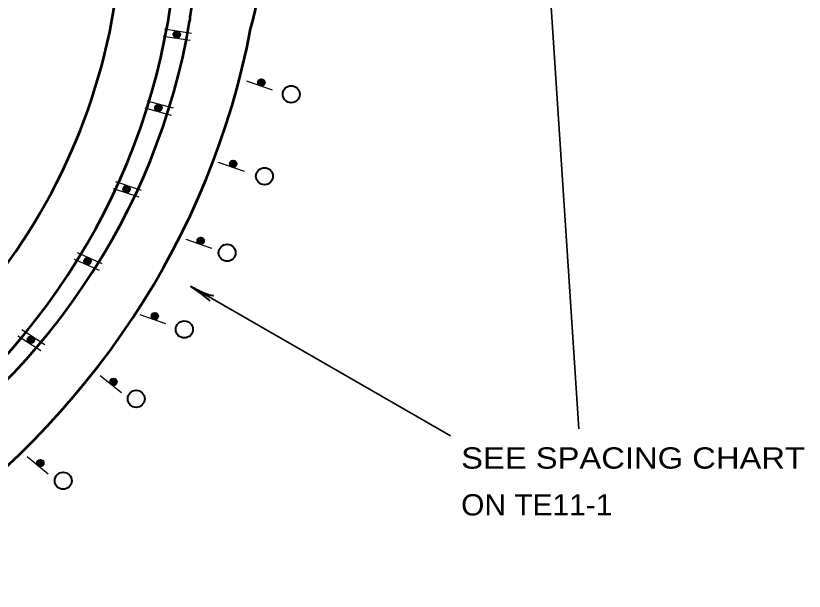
# Model space of a CAD drawing. Extents: x 393 to 1249, y -102 to 530.
# Drawn here: x 1022 to 1112, y 163.3 to 229 of the extents above; entities that cross this region are included whole.
import ezdxf

# ---------------------------------------------------------------- set-up
doc = ezdxf.new("R2010")
doc.units = 0
doc.header["$LTSCALE"] = 0.97
doc.layers.add('1', color=7, linetype='Continuous', lineweight=40)
doc.layers.add('4', color=7, linetype='Continuous', lineweight=25)

msp = doc.modelspace()

# ---------------------------------------------------------------- linework, layer by layer
at = {"layer": '1', "lineweight": 35}
for p, q in [((1078.9776, 294.0742), (1086.2967, 181.8469)), ((1041.9751, 198.1117), (1071.6584, 181.0337))]:
    msp.add_line(p, q, dxfattribs=at)
at = {"layer": '1'}
for centre, radius in [((1040.4098, 226.8492), 0.3791), ((1040.3987, 226.8411), 0.35), ((1040.4002, 226.8507), 0.3305), ((1040.4321, 226.8653), 0.3402), ((1040.4098, 226.8492), 0.3013), ((1040.4098, 226.8492), 0.2819), ((1040.4002, 226.8507), 0.2722), ((1040.4002, 226.8507), 0.2527), ((1040.4018, 226.8603), 0.2335), ((1040.4033, 226.8699), 0.2138), ((1040.4033, 226.8699), 0.1944), ((1040.381, 226.8537), 0.1555), ((1040.4063, 226.8891), 0.175), ((1040.3902, 226.9113), 0.1555), ((1040.4013, 226.9194), 0.1461), ((1040.3932, 226.9305), 0.1166), ((1040.3906, 226.8522), 0.1069), ((1040.3947, 226.9401), 0.0977), ((1040.3962, 226.9497), 0.0778), ((1040.3993, 226.9689), 0.0583), ((1040.4023, 226.9881), 0.0389), ((1040.4054, 227.0073), 0.0194), ((1040.5503, 226.8663), 0.00972), ((1050.0663, 221.3738), 0.3791), ((1050.0542, 221.3985), 0.3402), ((1050.0723, 221.3615), 0.35), ((1050.0755, 221.3706), 0.3305), ((1050.0663, 221.3738), 0.3013), ((1050.0663, 221.3738), 0.2819), ((1050.0755, 221.3706), 0.2722), ((1050.0755, 221.3706), 0.2527), ((1050.0786, 221.3798), 0.2335), ((1050.0818, 221.389), 0.2138), ((1050.0818, 221.389), 0.1944), ((1050.0881, 221.4074), 0.175), ((1050.0938, 221.3643), 0.1555), ((1049.9503, 221.4549), 0.00972), ((1050.1128, 221.4195), 0.1555), ((1050.1068, 221.4318), 0.1461), ((1050.0846, 221.3675), 0.1069), ((1050.1191, 221.4378), 0.1166), ((1050.1223, 221.447), 0.0977), ((1050.1255, 221.4562), 0.0778), ((1050.1318, 221.4746), 0.0583), ((1050.1381, 221.493), 0.0389), ((1050.1445, 221.5114), 0.0194), ((1053.4735, 220.025), 0.972), ((1038.3112, 218.4741), 0.3791), ((1038.2993, 218.4673), 0.35), ((1038.3018, 218.4767), 0.3305), ((1038.335, 218.4879), 0.3402), ((1038.3112, 218.4741), 0.3013), ((1038.3112, 218.4741), 0.2819), ((1038.3018, 218.4767), 0.2722), ((1038.3018, 218.4767), 0.2527), ((1038.3043, 218.486), 0.2335), ((1038.3068, 218.4954), 0.2138), ((1038.3068, 218.4954), 0.1944), ((1038.2981, 218.538), 0.1555), ((1038.31, 218.5449), 0.1461), ((1038.283, 218.4817), 0.1555), ((1038.3119, 218.5142), 0.175), ((1038.2924, 218.4792), 0.1069), ((1038.3031, 218.5568), 0.1166), ((1038.3057, 218.5662), 0.0977), ((1038.3082, 218.5756), 0.0778), ((1038.3132, 218.5943), 0.0583), ((1038.3182, 218.6131), 0.0389), ((1038.3233, 218.6319), 0.0194), ((1038.4527, 218.4765), 0.00972), ((1046.857, 212.084), 0.3791), ((1046.845, 212.1087), 0.3402), ((1046.8631, 212.0716), 0.35), ((1046.8662, 212.0808), 0.3305), ((1046.857, 212.084), 0.3013), ((1046.857, 212.084), 0.2819), ((1046.8662, 212.0808), 0.2722), ((1046.8662, 212.0808), 0.2527), ((1046.8694, 212.09), 0.2335), ((1046.8726, 212.0992), 0.2138), ((1046.8726, 212.0992), 0.1944), ((1046.8789, 212.1176), 0.175), ((1046.8846, 212.0745), 0.1555), ((1046.741, 212.1651), 0.00972), ((1046.9036, 212.1297), 0.1555), ((1046.8976, 212.142), 0.1461), ((1046.8754, 212.0777), 0.1069), ((1046.9099, 212.148), 0.1166), ((1046.9131, 212.1572), 0.0977), ((1046.9163, 212.1664), 0.0778), ((1046.9226, 212.1848), 0.0583), ((1046.9289, 212.2032), 0.0389), ((1046.9352, 212.2216), 0.0194), ((1050.4239, 210.6728), 0.972), ((1034.6835, 209.1901), 0.3791), ((1034.6712, 209.1838), 0.35), ((1034.6742, 209.1931), 0.3305), ((1034.708, 209.2026), 0.3402), ((1034.6835, 209.1901), 0.3013), ((1034.6835, 209.1901), 0.2819), ((1034.6742, 209.1931), 0.2722), ((1034.6742, 209.1931), 0.2527), ((1034.6772, 209.2023), 0.2335), ((1034.6802, 209.2116), 0.2138), ((1034.6802, 209.2116), 0.1944), ((1034.6557, 209.1991), 0.1555), ((1034.6863, 209.2301), 0.175), ((1034.6738, 209.2545), 0.1555), ((1034.686, 209.2608), 0.1461), ((1034.665, 209.1961), 0.1069), ((1034.6798, 209.273), 0.1166), ((1034.6828, 209.2823), 0.0977), ((1034.6858, 209.2915), 0.0778), ((1034.6918, 209.31), 0.0583), ((1034.6978, 209.3285), 0.0389), ((1034.7038, 209.347), 0.0194), ((1034.8249, 209.185), 0.00972), ((1043.1412, 203.3009), 0.3791), ((1043.1291, 203.3256), 0.3402), ((1043.1472, 203.2886), 0.35), ((1043.1504, 203.2978), 0.3305), ((1043.1412, 203.3009), 0.3013), ((1043.1412, 203.3009), 0.2819), ((1043.1504, 203.2978), 0.2722), ((1043.1504, 203.2978), 0.2527), ((1043.1535, 203.307), 0.2335), ((1043.1567, 203.3161), 0.2138), ((1043.1567, 203.3161), 0.1944), ((1043.163, 203.3345), 0.175), ((1043.1687, 203.2914), 0.1555), ((1043.0252, 203.382), 0.00972), ((1043.1877, 203.3466), 0.1555), ((1043.1817, 203.3589), 0.1461), ((1043.1595, 203.2946), 0.1069), ((1043.1941, 203.365), 0.1166), ((1043.1972, 203.3742), 0.0977), ((1043.2004, 203.3833), 0.0778), ((1043.2067, 203.4017), 0.0583), ((1043.213, 203.4201), 0.0389), ((1043.2194, 203.4385), 0.0194), ((1046.1544, 201.9306), 0.972), ((1030.2192, 200.9641), 0.3791), ((1030.2064, 200.9592), 0.35), ((1030.2103, 200.9681), 0.3305), ((1030.2449, 200.974), 0.3402), ((1030.2192, 200.9641), 0.3013), ((1030.2192, 200.9641), 0.2819), ((1030.2103, 200.9681), 0.2722), ((1030.2103, 200.9681), 0.2527), ((1030.2143, 200.977), 0.2335), ((1030.2182, 200.9858), 0.2138), ((1030.2182, 200.9858), 0.1944), ((1030.1926, 200.976), 0.1555), ((1030.2261, 201.0036), 0.175), ((1030.2163, 201.0293), 0.1555), ((1030.2291, 201.0342), 0.1461), ((1030.2014, 200.972), 0.1069), ((1030.2242, 201.047), 0.1166), ((1030.2281, 201.0559), 0.0977), ((1030.2321, 201.0648), 0.0778), ((1030.24, 201.0825), 0.0583), ((1030.2479, 201.1003), 0.0389), ((1030.2558, 201.1181), 0.0194), ((1030.3593, 200.9443), 0.00972), ((1037.9051, 194.6868), 0.3791), ((1037.893, 194.7115), 0.3402), ((1037.9111, 194.6745), 0.35), ((1037.9143, 194.6837), 0.3305), ((1037.9051, 194.6868), 0.3013), ((1037.9051, 194.6868), 0.2819), ((1037.9143, 194.6837), 0.2722), ((1037.9143, 194.6837), 0.2527), ((1037.9174, 194.6928), 0.2335), ((1037.9206, 194.702), 0.2138), ((1037.9206, 194.702), 0.1944), ((1037.9269, 194.7204), 0.175), ((1037.9327, 194.6773), 0.1555), ((1037.7891, 194.7679), 0.00972), ((1037.9516, 194.7325), 0.1555), ((1037.9456, 194.7448), 0.1461), ((1037.9235, 194.6805), 0.1069), ((1037.958, 194.7509), 0.1166), ((1037.9611, 194.76), 0.0977), ((1037.9643, 194.7692), 0.0778), ((1037.9706, 194.7876), 0.0583), ((1037.977, 194.806), 0.0389), ((1037.9833, 194.8244), 0.0194), ((1041.275, 193.1884), 0.972), ((1023.7523, 191.9966), 0.3791), ((1023.7388, 191.9938), 0.35), ((1023.7441, 192.0019), 0.3305), ((1023.7792, 192.0023), 0.3402), ((1023.7523, 191.9966), 0.3013), ((1023.7523, 191.9966), 0.2819), ((1023.7441, 192.0019), 0.2722), ((1023.7441, 192.0019), 0.2527), ((1023.7494, 192.0101), 0.2335), ((1023.7547, 192.0182), 0.2138), ((1023.7547, 192.0182), 0.1944), ((1023.7278, 192.0125), 0.1555), ((1023.7653, 192.0345), 0.175), ((1023.7596, 192.0614), 0.1555), ((1023.773, 192.0643), 0.1461), ((1023.736, 192.0072), 0.1069), ((1023.7702, 192.0777), 0.1166), ((1023.7755, 192.0859), 0.0977), ((1023.7807, 192.094), 0.0778), ((1023.7913, 192.1103), 0.0583), ((1023.8019, 192.1266), 0.0389), ((1023.8125, 192.1429), 0.0194), ((1023.8876, 191.9551), 0.00972), ((1033.188, 187.1869), 0.3791), ((1033.1894, 187.1732), 0.35), ((1033.1851, 187.2142), 0.3402), ((1033.1955, 187.1807), 0.3305), ((1033.188, 187.1869), 0.3013), ((1033.188, 187.1869), 0.2819), ((1033.1955, 187.1807), 0.2722), ((1033.1955, 187.1807), 0.2527), ((1033.2016, 187.1883), 0.2335), ((1033.2078, 187.1958), 0.2138), ((1033.2078, 187.1958), 0.1944), ((1033.22, 187.211), 0.175), ((1033.2106, 187.1685), 0.1555), ((1033.2473, 187.2138), 0.1555), ((1033.2031, 187.1746), 0.1069), ((1033.1067, 187.3027), 0.00972), ((1033.2459, 187.2275), 0.1461), ((1033.2596, 187.2289), 0.1166), ((1033.2657, 187.2365), 0.0977), ((1033.2718, 187.244), 0.0778), ((1033.284, 187.2592), 0.0583), ((1033.2963, 187.2743), 0.0389), ((1033.3085, 187.2894), 0.0194), ((1035.7857, 185.2594), 0.972), ((1024.8397, 177.9252), 0.3791), ((1024.8411, 177.9116), 0.35), ((1024.8368, 177.9526), 0.3402), ((1024.8473, 177.9191), 0.3305), ((1024.8397, 177.9252), 0.3013), ((1024.8397, 177.9252), 0.2819), ((1024.8473, 177.9191), 0.2722), ((1024.8473, 177.9191), 0.2527), ((1024.8534, 177.9267), 0.2335), ((1024.8595, 177.9342), 0.2138), ((1024.8595, 177.9342), 0.1944), ((1024.8717, 177.9493), 0.175), ((1024.8624, 177.9069), 0.1555), ((1024.8991, 177.9522), 0.1555), ((1024.8548, 177.913), 0.1069), ((1024.7584, 178.0411), 0.00972), ((1024.8976, 177.9659), 0.1461), ((1024.9113, 177.9673), 0.1166), ((1024.9174, 177.9749), 0.0977), ((1024.9235, 177.9824), 0.0778), ((1024.9358, 177.9975), 0.0583), ((1024.948, 178.0126), 0.0389), ((1024.9602, 178.0277), 0.0194), ((1027.4501, 175.9072), 0.972)]:
    msp.add_circle(centre, radius, dxfattribs=at)
at = {"layer": '1', "lineweight": 53}
for centre, radius, start, end in [((859.1336, 276.1484), 195.8532, 345.61191, 346.59757), ((1051.7197, 227.8874), 9.8478, 165.94117, 177.28334)]:
    msp.add_arc(centre, radius, start, end, dxfattribs=at)
for centre, major_axis, ratio, start_param, end_param in [((953.2504, 242.7846), (-80.225, 11.5377), 0.914497, 0.9311997, 3.1747556), ((953.2504, 242.7846), (-86.4787, 12.4371), 0.928319, 2.3193134, 3.1426457), ((953.2504, 242.7846), (-88.888, 12.7836), 0.91388, 2.3211234, 3.1212881), ((946.5814, 246.2426), (102.9232, -14.8021), 0.925624, 5.5007262, 6.2414789)]:
    msp.add_ellipse(centre, major_axis=major_axis, ratio=ratio, start_param=start_param, end_param=end_param, dxfattribs=at)
at = {"layer": '1'}
for centre, major_axis, ratio, start_param, end_param in [((1042.8165, 197.3904), (1.3947, -0.9994), 0.07063, 6.2823074, 8.5597026), ((1043.0283, 197.8156), (-1.5802, 0.734), 0.122415, 0.8963533, 3.1415927)]:
    msp.add_ellipse(centre, major_axis=major_axis, ratio=ratio, start_param=start_param, end_param=end_param, dxfattribs=at)
at = {"layer": '4'}
for p, q in [((1039.0078, 227.5042), (1042.08, 227.0176)), ((1038.8771, 226.6786), (1041.9493, 226.1919)), ((1051.3395, 220.5037), (1048.3984, 221.5165)), ((1036.9854, 219.2721), (1039.9898, 218.467)), ((1036.769, 218.4648), (1039.7735, 217.6596)), ((1048.1302, 211.2139), (1045.1891, 212.2266)), ((1033.4013, 210.0564), (1036.3595, 209.0952)), ((1033.143, 209.2615), (1036.1011, 208.3002)), ((1044.4143, 202.4308), (1041.4732, 203.4436)), ((1029.0345, 201.9597), (1031.8761, 200.6946)), ((1028.6945, 201.1961), (1031.536, 199.931)), ((1039.1783, 193.8168), (1036.2372, 194.8294)), ((1022.7379, 193.1652), (1025.3467, 191.4712)), ((1022.2825, 192.4642), (1024.8913, 190.7702)), ((1034.0867, 185.9338), (1031.6694, 187.8913)), ((1025.7385, 176.6722), (1023.3211, 178.6297))]:
    msp.add_line(p, q, dxfattribs=at)
for centre in [(1040.4194, 226.8476), (1050.0571, 221.377), (1038.3206, 218.4716), (1046.8479, 212.0872), (1034.6927, 209.1871), (1043.132, 203.3041), (1030.2281, 200.9602), (1037.8959, 194.69), (1023.7604, 191.9913), (1033.1804, 187.193), (1024.8321, 177.9314)]:
    msp.add_circle(centre, 0.3985, dxfattribs=at)

# ---------------------------------------------------------------- texts
at = {"layer": '1'}
for s, width, p in [('SEE SPACING CHART', 1.15, (1072.8727, 177.2911)), ('ON TE11-1', 1.05, (1072.8727, 171.9451))]:
    msp.add_text(s, height=2.43, dxfattribs=dict(at, width=width)).set_placement(p)

doc.saveas('drawing.dxf')
